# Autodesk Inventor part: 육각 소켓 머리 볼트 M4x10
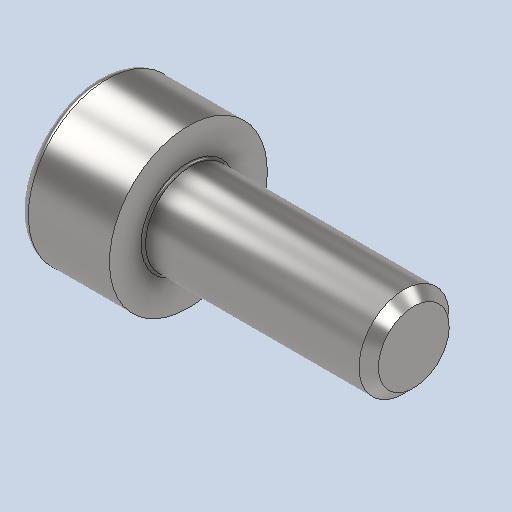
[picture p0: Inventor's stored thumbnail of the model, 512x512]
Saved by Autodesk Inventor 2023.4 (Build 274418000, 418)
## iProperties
Created: 2024-10
Part Number: 육각 소켓 머리 볼트 M4x10
Material: 강철, 연강
Description: 6각머리 태핑 나사
Document SubType Name: Modeling
Designer: EDU
Density: 7.85 g/cm^3
Appearance: 기본값
Author: jhkim
Sending System: Autodesk Inventor 2025
Preprocessor: ST-DEVELOPER v20
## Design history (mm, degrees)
feature "Solid1"
node "솔리드1"
